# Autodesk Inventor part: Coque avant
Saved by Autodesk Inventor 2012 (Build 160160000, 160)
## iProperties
Created: 2013-08
Part Number: Coque avant
Material: Default
Document SubType Name: Modeling
Designer: hilarion
Density: 1 g/cm^3
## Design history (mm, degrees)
node "Coque avant1"
node "Coque avant"
node "Base1"
